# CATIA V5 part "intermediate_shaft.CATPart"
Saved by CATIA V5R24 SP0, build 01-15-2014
Part number: IntermediateShaft
Bounding box of the stored display mesh (mm): x -12.5 to 12.5, y -12.409 to 12.409, z 0 to 190
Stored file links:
  D:\OneDrive\OneDrive - 한양대학교\문서\Teaching\2021\CAD\Final Exam\oscillation motion\intermediate_shaft.CATPart
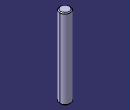
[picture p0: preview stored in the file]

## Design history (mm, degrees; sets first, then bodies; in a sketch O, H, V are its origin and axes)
Body1 (main body)
  Sketch1 on xy-plane, origin (0, 0, 0), H (1, 0, 0), V (0, 1, 0)
    circle A1 centre (0, 0) radius 12.5
    radius A1 = 12.5
  Pad1: profile Sketch1, direction (0, 0, 1), length 190
  Chamfer1: length 2, angle 45, on end face of Pad1; edge [start face of Pad1 | face of Pad1 from Sketch1.A1]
